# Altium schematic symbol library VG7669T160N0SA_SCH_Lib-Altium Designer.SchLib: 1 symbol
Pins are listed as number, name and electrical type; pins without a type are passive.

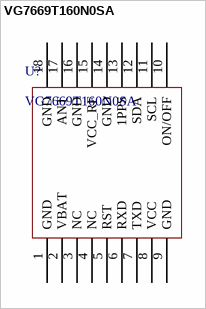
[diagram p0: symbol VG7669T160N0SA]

## VG7669T160N0SA
designator U?
pins: 1 GND, 2 VBAT, 3 NC, 4 NC, 5 RST, 6 RXD, 7 TXD, 8 VCC, 9 GND, 10 ON/OFF, 11 SCL, 12 SDA, 13 1PPS, 14 GND, 15 VCC_RF, 16 GND, 17 ANT, 18 GND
